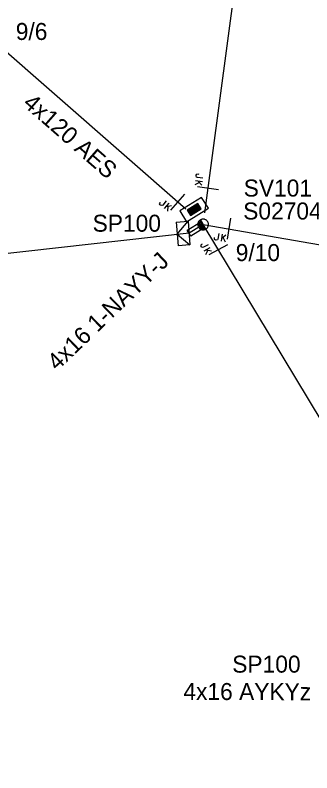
# Model space of a CAD drawing. Extents: x -788458 to -786145, y -1154772 to -1152372.
# Drawn here: x -786412.38 to -786394.96, y -1153490.54 to -1153445.99 of the extents above; entities that cross this region are included whole.
import ezdxf

# ---------------------------------------------------------------- set-up
doc = ezdxf.new("R2010")
doc.units = 0
for name, color, linetype in [('Vrstva 1', 7, 'Continuous'), ('Vrstva 12', 7, 'Continuous'), ('Vrstva 13', 7, 'Continuous'), ('Vrstva 15', 7, 'Continuous'), ('Vrstva 18', 7, 'Continuous'), ('Vrstva 2', 7, 'Continuous'), ('Vrstva 20', 7, 'Continuous'), ('Vrstva 28', 7, 'Continuous'), ('Vrstva 29', 7, 'Continuous'), ('Vrstva 30', 7, 'Continuous'), ('Vrstva 31', 7, 'Continuous'), ('Vrstva 33', 7, 'Continuous'), ('Vrstva 50', 7, 'Continuous'), ('Vrstva 51', 7, 'Continuous'), ('Vrstva 52', 7, 'Continuous'), ('Vrstva 54', 7, 'Continuous'), ('Vrstva 55', 7, 'Continuous'), ('Vrstva 59', 7, 'Continuous'), ('Vrstva 8', 7, 'Continuous'), ('Vrstva 9', 7, 'Continuous')]:
    doc.layers.add(name, color=color, linetype=linetype)

# ---------------------------------------------------------------- blocks, each defined once
blk = doc.blocks.new('NN440')
at = {"layer": 'Vrstva 2'}
for points in [[(0.631, -0.004), (0.627, 0.062), (0.617, 0.127), (0.6, 0.191), (0.577, 0.252), (0.547, 0.311), (0.511, 0.366), (0.469, 0.417), (0.423, 0.464), (0.371, 0.505), (0.316, 0.542), (0.257, 0.571), (0.196, 0.595), (0.132, 0.612), (0.067, 0.622), (0.001, 0.626), (-0.065, 0.622), (-0.13, 0.612), (-0.194, 0.595), (-0.255, 0.571), (-0.314, 0.542), (-0.369, 0.505), (-0.42, 0.464), (-0.467, 0.417), (-0.509, 0.366), (-0.544, 0.311), (-0.574, 0.252), (-0.598, 0.191), (-0.615, 0.127), (-0.626, 0.062), (-0.629, -0.004), (-0.626, -0.07), (-0.615, -0.135), (-0.598, -0.199), (-0.574, -0.26), (-0.544, -0.319), (-0.509, -0.374), (-0.467, -0.426), (-0.42, -0.472), (-0.369, -0.514), (-0.314, -0.55), (-0.255, -0.58), (-0.194, -0.603), (-0.13, -0.62), (-0.065, -0.631), (0.001, -0.634), (0.067, -0.631), (0.132, -0.62), (0.196, -0.603), (0.257, -0.58), (0.316, -0.55), (0.371, -0.514), (0.423, -0.472), (0.469, -0.426), (0.511, -0.374), (0.547, -0.319), (0.577, -0.26), (0.6, -0.199), (0.617, -0.135), (0.627, -0.07), (0.631, -0.004)], [(-0.631, 0), (0.629, 0)], [(-0.601, -0.177), (0.57, -0.177)], [(-0.513, -0.325), (0.501, -0.325)], [(-0.375, -0.473), (0.353, -0.473)]]:
    blk.add_lwpolyline(points, dxfattribs=at)
blk = doc.blocks.new('NN840')
at = {"layer": 'Vrstva 15'}
for points in [[(0.003, 0.619), (0.003, -0.631)], [(-0.538, -0.385), (-0.538, -0.71)], [(-0.332, -0.385), (-0.332, -0.798)], [(-0.332, -0.641), (-0.125, -0.385)], [(-0.745, -0.71), (-0.745, -0.66)], [(-0.73, -0.764), (-0.745, -0.71)], [(-0.657, -0.798), (-0.73, -0.764)], [(-0.627, -0.798), (-0.657, -0.798)], [(-0.558, -0.764), (-0.627, -0.798)], [(-0.538, -0.71), (-0.558, -0.764)], [(-0.263, -0.557), (-0.091, -0.798)]]:
    blk.add_lwpolyline(points, dxfattribs=at)
blk = doc.blocks.new('NN620')
at = {"layer": 'Vrstva 8'}
for points in [[(0.752, 0.004), (-0.748, 0.004)], [(-0.748, 0.004), (-0.748, -0.746)], [(0.752, -0.746), (0.752, 0.004)], [(0.368, -0.18), (-0.376, -0.18)], [(-0.376, -0.18), (-0.376, -0.558)], [(0.321, -0.227), (-0.329, -0.227)], [(-0.329, -0.227), (-0.329, -0.51)], [(0.274, -0.274), (-0.281, -0.274)], [(-0.281, -0.274), (-0.281, -0.463)], [(0.227, -0.321), (-0.234, -0.321)], [(-0.234, -0.321), (-0.234, -0.416)], [(-0.234, -0.416), (0.227, -0.416)], [(-0.193, -0.369), (0.185, -0.369)], [(0.227, -0.416), (0.227, -0.321)], [(0.274, -0.463), (0.274, -0.274)], [(0.321, -0.51), (0.321, -0.227)], [(0.368, -0.558), (0.368, -0.18)], [(-0.748, -0.746), (0.752, -0.746)], [(-0.376, -0.558), (0.368, -0.558)], [(-0.329, -0.51), (0.321, -0.51)], [(-0.281, -0.463), (0.274, -0.463)]]:
    blk.add_lwpolyline(points, dxfattribs=at)
blk = doc.blocks.new('NN630')
at = {"layer": 'Vrstva 9'}
for points in [[(-0.003, -0.7), (-0.703, 0)], [(-0.703, -0.7), (-0.703, 0), (0.697, 0), (0.697, -0.7)], [(-0.003, -0.7), (0.697, 0)], [(-0.703, -0.7), (0.697, -0.7)]]:
    blk.add_lwpolyline(points, dxfattribs=at)

msp = doc.modelspace()

# ---------------------------------------------------------------- linework, layer by layer
at = {"layer": 'Vrstva 1'}
for points in [[(-786401.25, -1153457.626), (-786396.77, -1153424.18), (-786400.51, -1153408.42)], [(-786401.34, -1153458.3), (-786378.53, -1153462.26)]]:
    msp.add_lwpolyline(points, dxfattribs=at)
at = {"layer": 'Vrstva 20'}
msp.add_lwpolyline([(-786402.275, -1153458.64), (-786401.445, -1153458.13), (-786401.235, -1153458.47), (-786402.065, -1153458.98)], close=True, dxfattribs=at)
at = {"layer": 'Vrstva 50'}
for points in [[(-786402.361, -1153457.407), (-786413.72, -1153447.47), (-786427.01, -1153429.09)], [(-786381.92, -1153490.54), (-786401.34, -1153458.3)]]:
    msp.add_lwpolyline(points, dxfattribs=at)
at = {"layer": 'Vrstva 52'}
msp.add_lwpolyline([(-786401.34, -1153458.3), (-786402.17, -1153458.81)], dxfattribs=at)
at = {"layer": 'Vrstva 59'}
msp.add_lwpolyline([(-786402.17, -1153458.81), (-786417.525, -1153460.541)], dxfattribs=at)

# ---------------------------------------------------------------- block references
at = {"layer": 'Vrstva 13', "xscale": 0.5, "yscale": 0.5, "rotation": -61.888747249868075}
msp.add_blockref('NN440', (-786401.34, -1153458.3), dxfattribs=at)
at = {"layer": 'Vrstva 18'}
for p, rotation in [((-786401.047, -1153456.168), -97.92032457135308), ((-786402.844, -1153456.985), -41.17937134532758), ((-786399.828, -1153458.54), -9.022068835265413), ((-786400.447, -1153459.783), -61.888747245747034)]:
    msp.add_blockref('NN840', p, dxfattribs=dict(at, rotation=rotation))
at = {"layer": 'Vrstva 28', "rotation": -148.19681601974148}
msp.add_blockref('NN620', (-786401.671, -1153457.74), dxfattribs=at)
at = {"layer": 'Vrstva 31', "rotation": -85.32755726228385}
msp.add_blockref('NN630', (-786402.17, -1153458.81), dxfattribs=at)

# ---------------------------------------------------------------- texts
at = {"layer": 'Vrstva 12'}
for s, p in [('9/6', (-786412.345, -1153447.454)), ('9/10', (-786399.425, -1153460.453))]:
    msp.add_text(s, height=1, dxfattribs=at).set_placement(p)
at = {"layer": 'Vrstva 29'}
msp.add_text('S027040', height=1, dxfattribs=at).set_placement((-786398.988, -1153458.008))
at = {"layer": 'Vrstva 30'}
msp.add_text('SV101', height=1, dxfattribs=at).set_placement((-786398.958, -1153456.66))
at = {"layer": 'Vrstva 33'}
for p in [(-786407.831, -1153458.727), (-786399.631, -1153484.649)]:
    msp.add_text('SP100', height=1, dxfattribs=at).set_placement(p)
at = {"layer": 'Vrstva 51'}
msp.add_text('4x120 AES', height=1, rotation=318.771, dxfattribs=at).set_placement((-786411.989, -1153451.272))
at = {"layer": 'Vrstva 54'}
msp.add_text('4x16 1-NAYY-J', height=1, rotation=43.847, dxfattribs=at).set_placement((-786409.914, -1153466.946))
at = {"layer": 'Vrstva 55'}
msp.add_text('4x16 AYKYz', height=1, rotation=359.86, dxfattribs=at).set_placement((-786402.502, -1153486.253))

doc.saveas('drawing.dxf')
